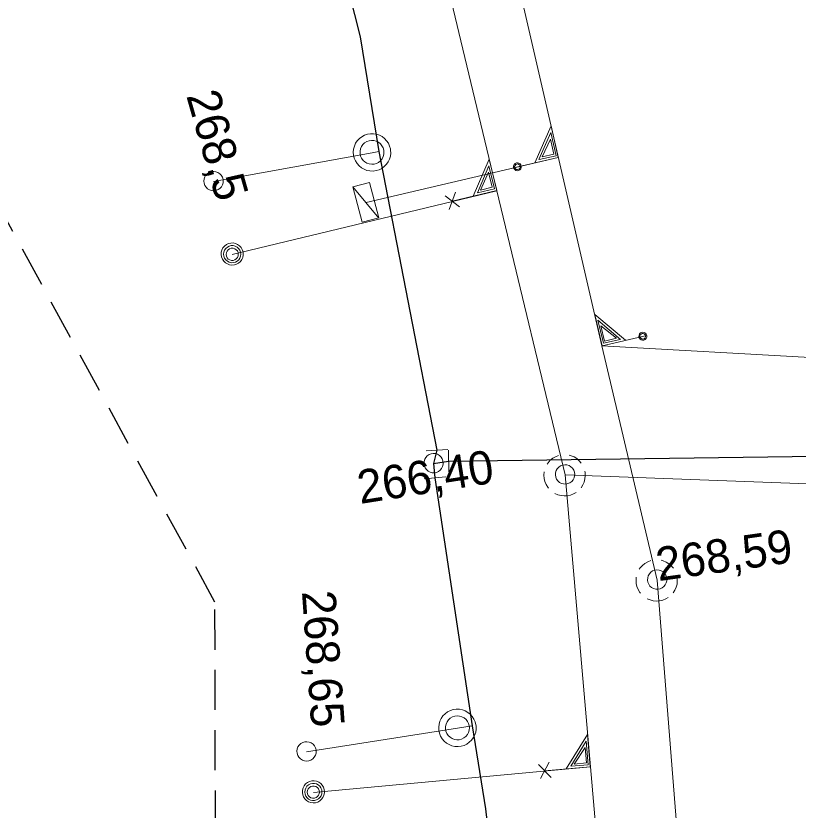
# Model space of a CAD drawing. Extents: x -732074 to -731966, y -1048695 to -1047982.
# Drawn here: x -732000.3 to -731981.61, y -1048616.96 to -1048598 of the extents above; entities that cross this region are included whole.
import ezdxf

# ---------------------------------------------------------------- set-up
doc = ezdxf.new("R2010")
doc.units = 0
doc.header["$LTSCALE"] = 0.32
doc.linetypes.add('MEDIUM_DASHED', pattern=[4.5, 3, -1.5])
doc.layers.add('1', color=7, linetype='Continuous')
for name, color, linetype, lineweight in [('18', 7, 'Continuous', 13), ('20', 7, 'Continuous', 13), ('49', 7, 'Continuous', 13), ('63', 7, 'MEDIUM_DASHED', 25), ('8', 7, 'Continuous', 13)]:
    doc.layers.add(name, color=color, linetype=linetype, lineweight=lineweight)

msp = doc.modelspace()

# ---------------------------------------------------------------- linework, layer by layer
at = {"layer": '18'}
for p, q in [((-731992.245, -1048602.085), (-731991.626, -1048602.827)), ((-731990.041, -1048602.298), (-731989.701, -1048602.561)), ((-731989.949, -1048602.624), (-731989.799, -1048602.207)), ((-731987.769, -1048616.21), (-731987.558, -1048615.819)), ((-731987.811, -1048615.873), (-731987.514, -1048616.184))]:
    msp.add_line(p, q, dxfattribs=at)
for points in [[(-731988.408, -1048601.626), (-731987.341, -1048601.38), (-731987.515, -1048600.629), (-731987.904, -1048601.51)], [(-731987.8, -1048601.433), (-731987.395, -1048601.34), (-731987.522, -1048600.788), (-731987.802, -1048601.434)], [(-731987.73, -1048601.369), (-731987.445, -1048601.303), (-731987.528, -1048600.942), (-731987.729, -1048601.37)], [(-731989.878, -1048602.424), (-731988.812, -1048602.168), (-731988.992, -1048601.419), (-731989.374, -1048602.303)], [(-731989.201, -1048602.161), (-731988.918, -1048602.093), (-731989.004, -1048601.732), (-731989.2, -1048602.163)], [(-731985.23, -1048605.629), (-731986.297, -1048605.877), (-731986.472, -1048605.128), (-731985.734, -1048605.746)], [(-731985.86, -1048605.724), (-731986.265, -1048605.819), (-731986.394, -1048605.268), (-731985.859, -1048605.724)], [(-731985.953, -1048605.698), (-731986.237, -1048605.764), (-731986.322, -1048605.402), (-731985.953, -1048605.699)], [(-731987.333, -1048608.497), (-731987.404, -1048608.525), (-731987.471, -1048608.564), (-731987.531, -1048608.612), (-731987.582, -1048608.669), (-731987.606, -1048608.703)], [(-731986.792, -1048608.68), (-731986.842, -1048608.622), (-731986.9, -1048608.572), (-731986.965, -1048608.531), (-731987.036, -1048608.502), (-731987.085, -1048608.488)], [(-731987.678, -1048608.889), (-731987.684, -1048608.966), (-731987.679, -1048609.043), (-731987.662, -1048609.118), (-731987.633, -1048609.189), (-731987.593, -1048609.255), (-731987.577, -1048609.277)], [(-731986.797, -1048609.266), (-731986.756, -1048609.201), (-731986.725, -1048609.131), (-731986.706, -1048609.056), (-731986.698, -1048608.98), (-731986.703, -1048608.903), (-731986.709, -1048608.868)], [(-731987.42, -1048609.406), (-731987.35, -1048609.437), (-731987.275, -1048609.456), (-731987.199, -1048609.463), (-731987.122, -1048609.458), (-731987.047, -1048609.441), (-731986.975, -1048609.413), (-731986.915, -1048609.378)], [(-731985.133, -1048611.007), (-731985.204, -1048611.035), (-731985.271, -1048611.074), (-731985.331, -1048611.122), (-731985.382, -1048611.179), (-731985.406, -1048611.213)], [(-731984.592, -1048611.19), (-731984.642, -1048611.132), (-731984.7, -1048611.082), (-731984.765, -1048611.041), (-731984.836, -1048611.012), (-731984.885, -1048610.998)], [(-731985.478, -1048611.399), (-731985.483, -1048611.476), (-731985.478, -1048611.553), (-731985.462, -1048611.628), (-731985.433, -1048611.699), (-731985.392, -1048611.765), (-731985.377, -1048611.787)], [(-731984.597, -1048611.776), (-731984.556, -1048611.711), (-731984.525, -1048611.641), (-731984.505, -1048611.566), (-731984.498, -1048611.49), (-731984.503, -1048611.413), (-731984.509, -1048611.378)], [(-731985.22, -1048611.916), (-731985.15, -1048611.947), (-731985.075, -1048611.966), (-731984.999, -1048611.973), (-731984.922, -1048611.968), (-731984.847, -1048611.951), (-731984.775, -1048611.923), (-731984.715, -1048611.888)], [(-731987.668, -1048616.023), (-731986.577, -1048615.928), (-731986.643, -1048615.16), (-731987.152, -1048615.978)], [(-731987.039, -1048615.917), (-731986.625, -1048615.881), (-731986.674, -1048615.318), (-731987.04, -1048615.917)], [(-731986.96, -1048615.863), (-731986.67, -1048615.837), (-731986.702, -1048615.468), (-731986.959, -1048615.865)]]:
    msp.add_lwpolyline(points, dxfattribs=at)
for points in [[(-731989.272, -1048602.226), (-731988.867, -1048602.129), (-731988.999, -1048601.58)], [(-731988.338, -1048601.512), (-731988.369, -1048601.526), (-731988.393, -1048601.549), (-731988.408, -1048601.579), (-731988.41, -1048601.612), (-731988.402, -1048601.644), (-731988.382, -1048601.671), (-731988.354, -1048601.691), (-731988.322, -1048601.698), (-731988.289, -1048601.695), (-731988.258, -1048601.679), (-731988.236, -1048601.654), (-731988.224, -1048601.624), (-731988.224, -1048601.59), (-731988.234, -1048601.558), (-731988.255, -1048601.532), (-731988.285, -1048601.516), (-731988.318, -1048601.51)], [(-731988.33, -1048601.538), (-731988.356, -1048601.55), (-731988.374, -1048601.572), (-731988.383, -1048601.599), (-731988.378, -1048601.627), (-731988.363, -1048601.651), (-731988.34, -1048601.667), (-731988.312, -1048601.672), (-731988.284, -1048601.664), (-731988.263, -1048601.646), (-731988.25, -1048601.621), (-731988.249, -1048601.592), (-731988.259, -1048601.567), (-731988.28, -1048601.547), (-731988.307, -1048601.537)], [(-731991.847, -1048601.977), (-731991.627, -1048602.823), (-731992.025, -1048602.927), (-731992.246, -1048602.081)], [(-731994.865, -1048603.687), (-731994.87, -1048603.631), (-731994.887, -1048603.578), (-731994.916, -1048603.529), (-731994.955, -1048603.488), (-731995, -1048603.456), (-731995.053, -1048603.434), (-731995.108, -1048603.423), (-731995.164, -1048603.425), (-731995.218, -1048603.438), (-731995.269, -1048603.463), (-731995.314, -1048603.498), (-731995.35, -1048603.541), (-731995.375, -1048603.591), (-731995.39, -1048603.646), (-731995.392, -1048603.702), (-731995.384, -1048603.757), (-731995.363, -1048603.81), (-731995.331, -1048603.856), (-731995.291, -1048603.895), (-731995.244, -1048603.925), (-731995.191, -1048603.944), (-731995.135, -1048603.951), (-731995.078, -1048603.947), (-731995.024, -1048603.93), (-731994.975, -1048603.903), (-731994.934, -1048603.865), (-731994.901, -1048603.82), (-731994.877, -1048603.769), (-731994.865, -1048603.714)], [(-731994.924, -1048603.69), (-731994.929, -1048603.641), (-731994.948, -1048603.595), (-731994.975, -1048603.554), (-731995.012, -1048603.521), (-731995.056, -1048603.499), (-731995.105, -1048603.487), (-731995.154, -1048603.487), (-731995.201, -1048603.499), (-731995.245, -1048603.522), (-731995.282, -1048603.555), (-731995.311, -1048603.596), (-731995.328, -1048603.643), (-731995.333, -1048603.692), (-731995.326, -1048603.741), (-731995.309, -1048603.787), (-731995.281, -1048603.827), (-731995.244, -1048603.86), (-731995.2, -1048603.882), (-731995.151, -1048603.894), (-731995.102, -1048603.893), (-731995.054, -1048603.881), (-731995.011, -1048603.857), (-731994.973, -1048603.824), (-731994.946, -1048603.783), (-731994.929, -1048603.736)], [(-731994.983, -1048603.694), (-731994.989, -1048603.652), (-731995.005, -1048603.614), (-731995.034, -1048603.583), (-731995.068, -1048603.56), (-731995.108, -1048603.549), (-731995.151, -1048603.549), (-731995.191, -1048603.561), (-731995.225, -1048603.584), (-731995.252, -1048603.616), (-731995.269, -1048603.654), (-731995.274, -1048603.695), (-731995.269, -1048603.737), (-731995.25, -1048603.774), (-731995.223, -1048603.806), (-731995.186, -1048603.828), (-731995.147, -1048603.839), (-731995.105, -1048603.838), (-731995.065, -1048603.825), (-731995.031, -1048603.802), (-731995.004, -1048603.769), (-731994.988, -1048603.731)], [(-731985.343, -1048605.559), (-731985.374, -1048605.572), (-731985.399, -1048605.595), (-731985.413, -1048605.625), (-731985.416, -1048605.659), (-731985.407, -1048605.691), (-731985.387, -1048605.718), (-731985.359, -1048605.737), (-731985.327, -1048605.745), (-731985.294, -1048605.74), (-731985.265, -1048605.725), (-731985.242, -1048605.7), (-731985.229, -1048605.669), (-731985.229, -1048605.636), (-731985.24, -1048605.603), (-731985.261, -1048605.577), (-731985.29, -1048605.562), (-731985.323, -1048605.556)], [(-731985.338, -1048605.585), (-731985.364, -1048605.597), (-731985.383, -1048605.618), (-731985.39, -1048605.645), (-731985.386, -1048605.673), (-731985.372, -1048605.698), (-731985.348, -1048605.713), (-731985.32, -1048605.717), (-731985.293, -1048605.71), (-731985.271, -1048605.693), (-731985.259, -1048605.667), (-731985.257, -1048605.639), (-731985.267, -1048605.613), (-731985.288, -1048605.593), (-731985.314, -1048605.584)], [(-731986.949, -1048608.949), (-731986.955, -1048608.897), (-731986.973, -1048608.847), (-731987.001, -1048608.803), (-731987.039, -1048608.766), (-731987.084, -1048608.739), (-731987.134, -1048608.723), (-731987.186, -1048608.718), (-731987.238, -1048608.725), (-731987.287, -1048608.744), (-731987.331, -1048608.774), (-731987.366, -1048608.813), (-731987.392, -1048608.858), (-731987.407, -1048608.909), (-731987.41, -1048608.961), (-731987.402, -1048609.013), (-731987.381, -1048609.061), (-731987.351, -1048609.104), (-731987.311, -1048609.139), (-731987.265, -1048609.163), (-731987.214, -1048609.177), (-731987.162, -1048609.179), (-731987.11, -1048609.169), (-731987.062, -1048609.147), (-731987.02, -1048609.115), (-731986.987, -1048609.075), (-731986.963, -1048609.028), (-731986.951, -1048608.977)], [(-731984.749, -1048611.459), (-731984.755, -1048611.407), (-731984.772, -1048611.357), (-731984.801, -1048611.313), (-731984.839, -1048611.276), (-731984.884, -1048611.249), (-731984.934, -1048611.233), (-731984.986, -1048611.228), (-731985.038, -1048611.235), (-731985.087, -1048611.254), (-731985.13, -1048611.284), (-731985.166, -1048611.323), (-731985.192, -1048611.368), (-731985.206, -1048611.419), (-731985.21, -1048611.471), (-731985.201, -1048611.523), (-731985.181, -1048611.571), (-731985.151, -1048611.614), (-731985.111, -1048611.649), (-731985.065, -1048611.673), (-731985.014, -1048611.687), (-731984.962, -1048611.689), (-731984.91, -1048611.679), (-731984.862, -1048611.657), (-731984.82, -1048611.625), (-731984.787, -1048611.585), (-731984.763, -1048611.538), (-731984.75, -1048611.487)], [(-731992.926, -1048616.527), (-731992.931, -1048616.471), (-731992.948, -1048616.418), (-731992.977, -1048616.369), (-731993.016, -1048616.328), (-731993.061, -1048616.296), (-731993.114, -1048616.274), (-731993.169, -1048616.263), (-731993.225, -1048616.265), (-731993.279, -1048616.278), (-731993.33, -1048616.303), (-731993.375, -1048616.338), (-731993.411, -1048616.381), (-731993.436, -1048616.431), (-731993.451, -1048616.486), (-731993.453, -1048616.542), (-731993.445, -1048616.597), (-731993.424, -1048616.65), (-731993.392, -1048616.696), (-731993.352, -1048616.735), (-731993.304, -1048616.765), (-731993.252, -1048616.784), (-731993.196, -1048616.791), (-731993.139, -1048616.787), (-731993.085, -1048616.77), (-731993.036, -1048616.743), (-731992.995, -1048616.705), (-731992.962, -1048616.66), (-731992.938, -1048616.609), (-731992.926, -1048616.554)], [(-731992.985, -1048616.53), (-731992.99, -1048616.481), (-731993.009, -1048616.435), (-731993.036, -1048616.394), (-731993.073, -1048616.361), (-731993.117, -1048616.339), (-731993.166, -1048616.327), (-731993.215, -1048616.327), (-731993.262, -1048616.339), (-731993.306, -1048616.362), (-731993.343, -1048616.395), (-731993.372, -1048616.436), (-731993.389, -1048616.483), (-731993.394, -1048616.532), (-731993.387, -1048616.581), (-731993.37, -1048616.627), (-731993.342, -1048616.667), (-731993.304, -1048616.7), (-731993.261, -1048616.722), (-731993.212, -1048616.734), (-731993.163, -1048616.733), (-731993.115, -1048616.721), (-731993.071, -1048616.697), (-731993.034, -1048616.664), (-731993.007, -1048616.623), (-731992.99, -1048616.576)], [(-731993.044, -1048616.534), (-731993.049, -1048616.492), (-731993.066, -1048616.454), (-731993.095, -1048616.423), (-731993.129, -1048616.4), (-731993.169, -1048616.389), (-731993.212, -1048616.389), (-731993.252, -1048616.401), (-731993.286, -1048616.424), (-731993.313, -1048616.456), (-731993.33, -1048616.494), (-731993.335, -1048616.535), (-731993.33, -1048616.577), (-731993.311, -1048616.614), (-731993.284, -1048616.646), (-731993.247, -1048616.668), (-731993.208, -1048616.679), (-731993.166, -1048616.678), (-731993.125, -1048616.665), (-731993.092, -1048616.642), (-731993.065, -1048616.609), (-731993.049, -1048616.571)]]:
    msp.add_lwpolyline(points, close=True, dxfattribs=at)
at = {"layer": '20'}
for points in [[(-731987.18, -1048608.96), (-731988.807, -1048602.179), (-731992.473, -1048586.913), (-731996.42, -1048570.48)], [(-731987.18, -1048608.96), (-731988.807, -1048602.179), (-731992.473, -1048586.913), (-731996.42, -1048570.48)], [(-731984.98, -1048611.47), (-731986.302, -1048605.878), (-731994.199, -1048571.66)], [(-731984.98, -1048611.47), (-731986.302, -1048605.878), (-731994.199, -1048571.66)], [(-731984.62, -1048638.44), (-731986.574, -1048615.933), (-731987.18, -1048608.96)], [(-731967.059, -1048609.698), (-731974.517, -1048609.425), (-731987.18, -1048608.96)], [(-731984.62, -1048638.44), (-731986.574, -1048615.933), (-731987.18, -1048608.96)], [(-731967.059, -1048609.698), (-731974.517, -1048609.425), (-731987.18, -1048608.96)], [(-731969.16, -1048637.94), (-731982.899, -1048637.629), (-731984.98, -1048611.47)], [(-731969.16, -1048637.94), (-731982.899, -1048637.629), (-731984.98, -1048611.47)]]:
    msp.add_lwpolyline(points, dxfattribs=at)
at = {"layer": '49'}
for p, q in [((-731991.93, -1048602.46), (-731987.34, -1048601.381)), ((-731991.93, -1048602.46), (-731987.34, -1048601.381)), ((-731995.129, -1048603.7), (-731988.807, -1048602.179)), ((-731995.129, -1048603.7), (-731988.807, -1048602.179)), ((-731967.512, -1048606.947), (-731986.302, -1048605.878)), ((-731967.512, -1048606.947), (-731986.302, -1048605.878)), ((-731993.19, -1048616.54), (-731986.574, -1048615.933)), ((-731993.19, -1048616.54), (-731986.574, -1048615.933))]:
    msp.add_line(p, q, dxfattribs=at)
at = {"layer": '63'}
msp.add_lwpolyline([(-731995.365, -1048690.893), (-731995.541, -1048612.001), (-732022.871, -1048561.911), (-732022.871, -1048561.909), (-732073.995, -1048412.717)], dxfattribs=at)
at = {"layer": '8'}
for p, q in [((-731991.625, -1048601.24), (-731991.789, -1048601.27)), ((-731991.789, -1048601.27), (-731995.574, -1048601.956)), ((-731989.98, -1048608.351), (-731990.495, -1048608.388)), ((-731989.962, -1048608.37), (-731989.955, -1048608.887)), ((-731990.03, -1048609.007), (-731990.545, -1048609.052)), ((-731989.75, -1048615.01), (-731993.352, -1048615.571)), ((-731989.399, -1048614.955), (-731989.75, -1048615.01))]:
    msp.add_line(p, q, dxfattribs=at)
at = {"layer": '8', "lineweight": 25}
for p, q in [((-731989.96, -1048608.629), (-731980.969, -1048608.51)), ((-731990.32, -1048608.69), (-731990.289, -1048609.03))]:
    msp.add_line(p, q, dxfattribs=at)
for points in [[(-732007.629, -1048549.38), (-732002.27, -1048563.66), (-731996.51, -1048580.99), (-731995.102, -1048586.543), (-731992.07, -1048598.5), (-731991.625, -1048601.24), (-731990.239, -1048608.37)], [(-731990.239, -1048608.37), (-731990.32, -1048608.69), (-731989.96, -1048608.629)], [(-731990.289, -1048609.03), (-731989.399, -1048614.955), (-731989.079, -1048616.929), (-731987.35, -1048632.04), (-731987.44, -1048636.45)]]:
    msp.add_lwpolyline(points, dxfattribs=at)
at = {"layer": '8'}
for points in [[(-731991.351, -1048601.179), (-731991.37, -1048601.108), (-731991.4, -1048601.042), (-731991.44, -1048600.981), (-731991.491, -1048600.928), (-731991.549, -1048600.883), (-731991.613, -1048600.849), (-731991.682, -1048600.826), (-731991.755, -1048600.814), (-731991.828, -1048600.814), (-731991.901, -1048600.826), (-731991.97, -1048600.85), (-731992.034, -1048600.885), (-731992.091, -1048600.929), (-731992.142, -1048600.983), (-731992.182, -1048601.044), (-731992.212, -1048601.11), (-731992.23, -1048601.182), (-731992.238, -1048601.254), (-731992.232, -1048601.327), (-731992.215, -1048601.398), (-731992.187, -1048601.465), (-731992.148, -1048601.527), (-731992.099, -1048601.583), (-731992.042, -1048601.628), (-731991.979, -1048601.664), (-731991.91, -1048601.69), (-731991.839, -1048601.704), (-731991.765, -1048601.706), (-731991.693, -1048601.696), (-731991.622, -1048601.674), (-731991.557, -1048601.641), (-731991.498, -1048601.597), (-731991.447, -1048601.545), (-731991.405, -1048601.486), (-731991.373, -1048601.419), (-731991.352, -1048601.349), (-731991.344, -1048601.277), (-731991.347, -1048601.204)], [(-731991.509, -1048601.208), (-731991.525, -1048601.152), (-731991.553, -1048601.1), (-731991.59, -1048601.055), (-731991.636, -1048601.019), (-731991.688, -1048600.991), (-731991.744, -1048600.976), (-731991.803, -1048600.973), (-731991.861, -1048600.981), (-731991.916, -1048601.001), (-731991.966, -1048601.033), (-731992.008, -1048601.073), (-731992.041, -1048601.121), (-731992.064, -1048601.175), (-731992.076, -1048601.233), (-731992.075, -1048601.291), (-731992.063, -1048601.348), (-731992.039, -1048601.402), (-731992.005, -1048601.45), (-731991.961, -1048601.488), (-731991.911, -1048601.519), (-731991.856, -1048601.537), (-731991.797, -1048601.545), (-731991.739, -1048601.541), (-731991.683, -1048601.524), (-731991.631, -1048601.498), (-731991.586, -1048601.46), (-731991.55, -1048601.414), (-731991.524, -1048601.362), (-731991.509, -1048601.305), (-731991.505, -1048601.247)], [(-731995.348, -1048601.904), (-731995.363, -1048601.854), (-731995.39, -1048601.808), (-731995.425, -1048601.77), (-731995.469, -1048601.74), (-731995.518, -1048601.721), (-731995.57, -1048601.715), (-731995.623, -1048601.719), (-731995.672, -1048601.735), (-731995.717, -1048601.763), (-731995.755, -1048601.8), (-731995.783, -1048601.845), (-731995.8, -1048601.894), (-731995.806, -1048601.946), (-731995.8, -1048601.998), (-731995.782, -1048602.048), (-731995.753, -1048602.091), (-731995.716, -1048602.128), (-731995.67, -1048602.156), (-731995.621, -1048602.171), (-731995.568, -1048602.176), (-731995.517, -1048602.168), (-731995.467, -1048602.149), (-731995.424, -1048602.119), (-731995.388, -1048602.08), (-731995.363, -1048602.035), (-731995.348, -1048601.984), (-731995.345, -1048601.932)], [(-731990.088, -1048608.679), (-731990.095, -1048608.627), (-731990.112, -1048608.577), (-731990.141, -1048608.533), (-731990.179, -1048608.496), (-731990.223, -1048608.469), (-731990.274, -1048608.453), (-731990.326, -1048608.448), (-731990.377, -1048608.455), (-731990.426, -1048608.474), (-731990.47, -1048608.504), (-731990.505, -1048608.543), (-731990.532, -1048608.588), (-731990.546, -1048608.639), (-731990.549, -1048608.691), (-731990.541, -1048608.743), (-731990.521, -1048608.791), (-731990.49, -1048608.834), (-731990.451, -1048608.869), (-731990.404, -1048608.893), (-731990.353, -1048608.907), (-731990.301, -1048608.909), (-731990.25, -1048608.899), (-731990.201, -1048608.877), (-731990.159, -1048608.845), (-731990.127, -1048608.805), (-731990.103, -1048608.758), (-731990.09, -1048608.707)], [(-731989.309, -1048614.93), (-731989.326, -1048614.859), (-731989.355, -1048614.791), (-731989.394, -1048614.73), (-731989.443, -1048614.675), (-731989.5, -1048614.629), (-731989.563, -1048614.593), (-731989.632, -1048614.568), (-731989.704, -1048614.555), (-731989.777, -1048614.553), (-731989.85, -1048614.563), (-731989.919, -1048614.585), (-731989.985, -1048614.619), (-731990.043, -1048614.662), (-731990.095, -1048614.714), (-731990.137, -1048614.774), (-731990.168, -1048614.84), (-731990.188, -1048614.911), (-731990.197, -1048614.983), (-731990.194, -1048615.057), (-731990.178, -1048615.128), (-731990.151, -1048615.196), (-731990.114, -1048615.259), (-731990.067, -1048615.315), (-731990.011, -1048615.362), (-731989.948, -1048615.4), (-731989.88, -1048615.427), (-731989.809, -1048615.443), (-731989.736, -1048615.446), (-731989.663, -1048615.438), (-731989.592, -1048615.418), (-731989.526, -1048615.386), (-731989.466, -1048615.344), (-731989.413, -1048615.293), (-731989.37, -1048615.235), (-731989.337, -1048615.169), (-731989.314, -1048615.1), (-731989.304, -1048615.027), (-731989.306, -1048614.955)], [(-731989.468, -1048614.955), (-731989.483, -1048614.898), (-731989.509, -1048614.846), (-731989.545, -1048614.8), (-731989.59, -1048614.762), (-731989.641, -1048614.734), (-731989.697, -1048614.717), (-731989.756, -1048614.713), (-731989.814, -1048614.72), (-731989.869, -1048614.738), (-731989.92, -1048614.769), (-731989.963, -1048614.808), (-731989.998, -1048614.855), (-731990.022, -1048614.908), (-731990.035, -1048614.966), (-731990.036, -1048615.024), (-731990.025, -1048615.082), (-731990.002, -1048615.136), (-731989.969, -1048615.184), (-731989.926, -1048615.224), (-731989.877, -1048615.256), (-731989.822, -1048615.276), (-731989.764, -1048615.285), (-731989.706, -1048615.282), (-731989.649, -1048615.267), (-731989.597, -1048615.241), (-731989.551, -1048615.205), (-731989.513, -1048615.159), (-731989.486, -1048615.108), (-731989.469, -1048615.052), (-731989.465, -1048614.994)], [(-731993.125, -1048615.525), (-731993.139, -1048615.474), (-731993.164, -1048615.427), (-731993.199, -1048615.388), (-731993.242, -1048615.358), (-731993.291, -1048615.338), (-731993.343, -1048615.33), (-731993.395, -1048615.333), (-731993.445, -1048615.348), (-731993.49, -1048615.374), (-731993.529, -1048615.41), (-731993.558, -1048615.454), (-731993.577, -1048615.503), (-731993.584, -1048615.556), (-731993.579, -1048615.607), (-731993.563, -1048615.658), (-731993.534, -1048615.702), (-731993.498, -1048615.74), (-731993.453, -1048615.768), (-731993.404, -1048615.785), (-731993.352, -1048615.791), (-731993.3, -1048615.785), (-731993.25, -1048615.767), (-731993.206, -1048615.738), (-731993.169, -1048615.699), (-731993.143, -1048615.655), (-731993.127, -1048615.605), (-731993.123, -1048615.552)]]:
    msp.add_lwpolyline(points, close=True, dxfattribs=at)

# ---------------------------------------------------------------- texts
at = {"layer": '1'}
for s, rotation, p in [('268,5 ', 286, (-731996.23, -1048599.903)), ('266,40', 9, (-731992.073, -1048609.655)), ('268,59', 8, (-731984.949, -1048611.498)), ('268,65', 274, (-731993.464, -1048611.743))]:
    msp.add_text(s, height=0.8, rotation=rotation, dxfattribs=at).set_placement(p)

doc.saveas('drawing.dxf')
